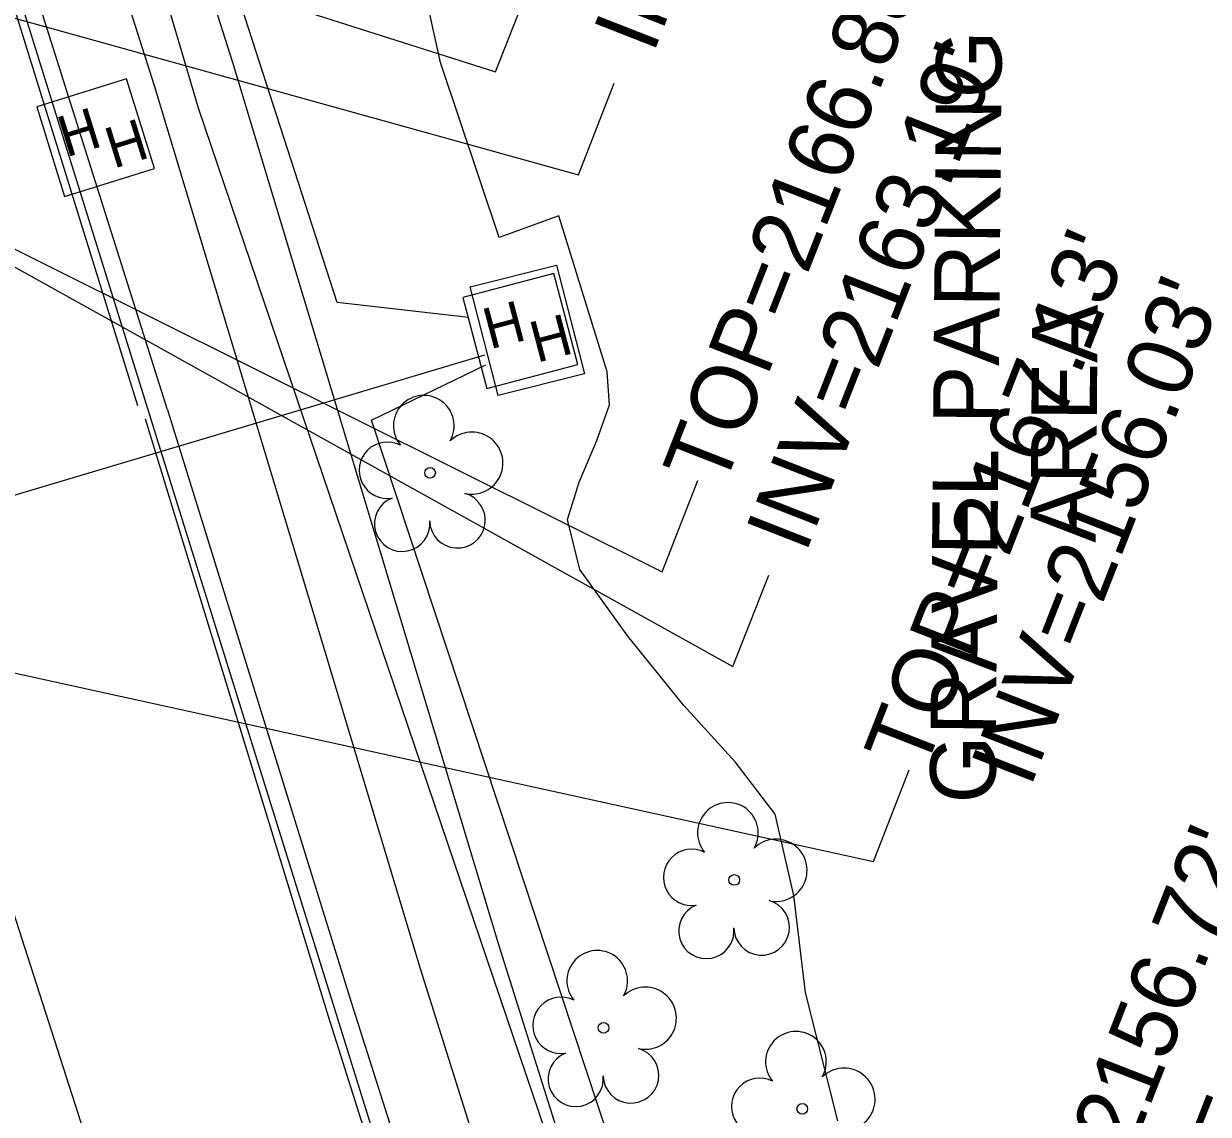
# Model space of a CAD drawing. Extents: x 945964 to 948456, y 631061 to 636061.
# Drawn here: x 946519.4 to 946591.8, y 633199.7 to 633266.4 of the extents above; entities that cross this region are included whole.
import ezdxf

# ---------------------------------------------------------------- set-up
doc = ezdxf.new("R2010")
doc.units = 0
for name, color, linetype in [('Exist Roads Curbs', 7, 'Continuous'), ('Exist Roads EOP', 7, 'Continuous'), ('Exist Roads EOP Other', 7, 'Continuous'), ('Exist Roads Soil', 7, 'Continuous'), ('Exist Roads Soil Text', 7, 'Continuous'), ('Exist Structure Minor Drop Inlet Top Elevation', 7, 'Continuous'), ('Exist Structure Minor Pipes HDPE 8 Inch Invert', 7, 'Continuous'), ('Exist Structure Minor Pipes RCP 15 Inch', 7, 'Continuous'), ('Exist Structure Minor Pipes RCP 15 Inch Invert', 7, 'Continuous'), ('Exist Structure Minor Storm Sewer Manhole Top Elevation', 7, 'Continuous'), ('Exist Utilities Power Hand Hole CELL', 7, 'Continuous'), ('Exist Utilities Power UG Cable SUE', 7, 'Continuous'), ('Exist Utilities Sanitary Sewer Manhole Top Elevation', 7, 'Continuous'), ('Exist Utilities Sanitary Sewer UG Line', 7, 'Continuous'), ('Exist Utilities Sanitary Sewer UG Line Invert Elevation', 7, 'Continuous'), ('Exist Vegetation Tree CELL', 7, 'Continuous')]:
    doc.layers.add(name, color=color, linetype=linetype)

# ---------------------------------------------------------------- blocks, each defined once
blk = doc.blocks.new('EXIST UTILITIES POWER HAND HOLE')
at = {"layer": 'Exist Utilities Power Hand Hole CELL'}
blk.add_line((0, 0), (0, 0), dxfattribs=at)
blk.add_lwpolyline([(-0.059, -0.0545), (0.056, -0.0545), (0.056, 0.0605), (-0.059, 0.0605), (-0.059, -0.0545)], dxfattribs=at)
for p in [(-0.0432, -0.0095), (0.0081, -0.0399)]:
    blk.add_text('H', height=0.05, dxfattribs=at).set_placement(p)
blk = doc.blocks.new('EXIST VEGETATION TREE')
at = {"layer": 'Exist Vegetation Tree CELL'}
blk.add_line((0, 0), (0, 0), dxfattribs=at)
blk.add_circle((0, 0), 0.00652, dxfattribs=at)
for centre, radius, start, end in [((-0.0077, 0.0575), 0.0371, 330.1651, 219.7134), ((0.051, 0.0118), 0.038, 257.1011, 134.1999), ((-0.0521, 0.0031), 0.0345, 62.6636, 279.3457), ((0.0335, -0.058), 0.034, 181.2822, 74.56), ((-0.0341, -0.0624), 0.0338, 111.5671, 6.231)]:
    blk.add_arc(centre, radius, start, end, dxfattribs=at)

msp = doc.modelspace()

# ---------------------------------------------------------------- linework, layer by layer
at = {"layer": 'Exist Roads Curbs'}
for points in [[(946528.173, 633242.813), (946519.471, 633270.371), (946509.322, 633303.583), (946500.657, 633331.201), (946493.21, 633355.616), (946482.885, 633388.484), (946473.858, 633417.469), (946471.117, 633427.051), (946471.079, 633427.584)], [(946528.173, 633242.813), (946539.398, 633206.598), (946551.941, 633167.098), (946565.823, 633126.711), (946580.796, 633084.714)]]:
    msp.add_lwpolyline(points, dxfattribs=at)
at = {"layer": 'Exist Roads EOP'}
for points in [[(946526.362, 633243.056), (946518.038, 633269.93), (946507.889, 633303.14), (946499.224, 633330.758), (946498.997, 633331.5)], [(946526.798, 633242.266), (946537.982, 633205.739), (946548.864, 633171.341), (946549.555, 633166.284), (946550.565, 633163.363), (946553.005, 633158.832), (946564.478, 633126.046), (946579.44, 633084.212), (946589.837, 633054.731), (946605.359, 633010.331), (946614.32, 632975.673), (946614.471, 632970.74), (946614.872, 632967.622), (946616.598, 632962.977), (946620.257, 632924.553), (946625.171, 632888.287)]]:
    msp.add_lwpolyline(points, dxfattribs=at)
at = {"layer": 'Exist Roads EOP Other'}
for points in [[(946591.702, 633083.259), (946591.261, 633084.479), (946582.486, 633109.691), (946574.439, 633132.347), (946565.854, 633156.511), (946558.066, 633179.438), (946548.416, 633210.116), (946541.598, 633232.775), (946532.148, 633264.101), (946524.202, 633289.058), (946514.963, 633319.771), (946502.946, 633357.906), (946492.055, 633393.132), (946482.703, 633423.175), (946481.345, 633427.978)], [(946586.534, 633082.85), (946577.769, 633108.032), (946569.727, 633130.673), (946561.131, 633154.87), (946553.313, 633177.884), (946543.637, 633208.646), (946536.811, 633231.332), (946527.372, 633262.621), (946519.426, 633287.579), (946510.185, 633318.3), (946498.173, 633356.416), (946487.279, 633391.65), (946477.91, 633421.751), (946476.533, 633426.618)], [(946546.672, 633250.326), (946551.951, 633251.661), (946553.662, 633245.02), (946548.384, 633243.684), (946546.672, 633250.326)]]:
    msp.add_lwpolyline(points, dxfattribs=at)
at = {"layer": 'Exist Roads Soil'}
msp.add_lwpolyline([(946569.131, 633199.346), (946567.167, 633207.189), (946566.442, 633213.13), (946565.313, 633218.103), (946562.858, 633221.3), (946559.724, 633224.747), (946556.3, 633228.981), (946553.37, 633233.051), (946552.621, 633236.105), (946553.326, 633238.389), (946554.415, 633240.931), (946555.178, 633243.117), (946555.043, 633245.132), (946552.085, 633254.667), (946548.444, 633253.341), (946544.861, 633264.042), (946542.73, 633273.669)], dxfattribs=at)
at = {"layer": 'Exist Structure Minor Pipes HDPE 8 Inch Invert'}
for points in [[(946467.606, 633289.102), (946548.225, 633263.48), (946550.413, 633269.067)], [(946463.765, 633282.086), (946553.283, 633257.187), (946555.471, 633262.774)]]:
    msp.add_lwpolyline(points, dxfattribs=at)
at = {"layer": 'Exist Structure Minor Pipes RCP 15 Inch'}
msp.add_line((946498.053, 633335.801), (946550.752, 633166.403), dxfattribs=at)
at = {"layer": 'Exist Structure Minor Pipes RCP 15 Inch Invert'}
msp.add_lwpolyline([(946500.96, 633261.476), (946562.726, 633227.115), (946564.914, 633232.702)], dxfattribs=at)
at = {"layer": 'Exist Structure Minor Storm Sewer Manhole Top Elevation'}
msp.add_lwpolyline([(946502.015, 633260.998), (946558.393, 633232.914), (946560.58, 633238.501)], dxfattribs=at)
at = {"layer": 'Exist Utilities Power UG Cable SUE'}
msp.add_line((946444.102, 633215.318), (946547.554, 633246.176), dxfattribs=at)
for points in [[(946635.138, 632865.796), (946629.467, 632896.547), (946595.835, 632887.236), (946588.047, 632902.071), (946565.484, 632967.5), (946565.842, 632977.615), (946565.32, 632980.272), (946555.599, 632997.55), (946522.142, 633095.32), (946521.351, 633107.95), (946521.635, 633110.72), (946553.29, 633127.22), (946568.203, 633134.976), (946566.108, 633154.955), (946530.059, 633261.253), (946518.065, 633301.872), (946482.924, 633416.058), (946475.992, 633414.937), (946451.492, 633482.539), (946451.321, 633490.535), (946420.978, 633516.119), (946400.783, 633553.039), (946391.57, 633575.171)], [(946546.563, 633248.461), (946538.541, 633249.367), (946514.276, 633324.415), (946485.263, 633416.881), (946486.731, 633425.033)], [(946629.745, 632987.223), (946623.927, 632988.64), (946610.653, 633023.709), (946594.589, 633083.481), (946566.88, 633162.75), (946540.629, 633242.179), (946547.619, 633245.565)]]:
    msp.add_lwpolyline(points, dxfattribs=at)
at = {"layer": 'Exist Utilities Sanitary Sewer Manhole Top Elevation'}
msp.add_lwpolyline([(946513.677, 633227.86), (946571.305, 633215.212), (946573.492, 633220.799)], dxfattribs=at)
at = {"layer": 'Exist Utilities Sanitary Sewer UG Line'}
msp.add_lwpolyline([(946513.677, 633227.86), (946598.486, 632963.771)], dxfattribs=at)

# ---------------------------------------------------------------- block references
at = {"layer": 'Exist Utilities Power Hand Hole CELL'}
for p, xscale, yscale, rotation in [((946523.893, 633259.33), 49.99999999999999, 49.99999999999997, 17.271023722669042), ((946549.837, 633247.508), 49.999999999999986, 49.99999999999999, 14.721093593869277)]:
    msp.add_blockref('EXIST UTILITIES POWER HAND HOLE', p, dxfattribs=dict(at, xscale=xscale, yscale=yscale, rotation=rotation))
at = {"layer": 'Exist Vegetation Tree CELL', "xscale": 50, "yscale": 50}
for p in [(946544.218, 633238.964), (946562.804, 633214.075), (946554.82, 633205.031), (946566.962, 633200.08)]:
    msp.add_blockref('EXIST VEGETATION TREE', p, dxfattribs=at)

# ---------------------------------------------------------------- texts
at = {"layer": 'Exist Roads Soil Text'}
for s, p in [('GRAVEL PARKING', (946578.761, 633218.737)), ('AREA', (946584.896, 633234.684))]:
    msp.add_text(s, height=4, rotation=89.51867, dxfattribs=at).set_placement(p)
at = {"layer": 'Exist Structure Minor Drop Inlet Top Elevation'}
msp.add_text("TOP=2165.37'", height=4, rotation=68.6189, dxfattribs=at).set_placement((946586.07, 633175.671))
at = {"layer": 'Exist Structure Minor Pipes HDPE 8 Inch Invert'}
msp.add_text("INV=2163.22'", height=4, rotation=68.6189, dxfattribs=at).set_placement((946557.844, 633264.504))
at = {"layer": 'Exist Structure Minor Pipes RCP 15 Inch Invert'}
for s, p in [("INV=2163.19'", (946567.158, 633233.962)), ("INV=2156.72'", (946582.678, 633186.101))]:
    msp.add_text(s, height=4, rotation=68.6189, dxfattribs=at).set_placement(p)
at = {"layer": 'Exist Structure Minor Storm Sewer Manhole Top Elevation'}
msp.add_text("TOP=2166.88'", height=4, rotation=68.6189, dxfattribs=at).set_placement((946562.105, 633237.864))
at = {"layer": 'Exist Utilities Sanitary Sewer Manhole Top Elevation'}
msp.add_text("TOP=2167.13'", height=4, rotation=68.6189, dxfattribs=at).set_placement((946574.399, 633220.568))
at = {"layer": 'Exist Utilities Sanitary Sewer UG Line Invert Elevation'}
msp.add_text("INV=2156.03'", height=4, rotation=68.6189, dxfattribs=at).set_placement((946580.893, 633219.642))

doc.saveas('drawing.dxf')
